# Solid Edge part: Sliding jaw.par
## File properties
Title: Sliding Jaw
Author: Deepak Maini
Template: Normal.par
Last saved by: Robert a Rhodes jr
Revision: 17
Application: Solid Edge
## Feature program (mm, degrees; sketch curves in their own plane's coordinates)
sketch used by "unnamed Protrusion 1" plane through (0, 0, 0) normal (0, -1, 0) x-axis (1, 0, 0)
  line (-34.0632, 44.45) -> (-34.0632, 0)
  line (-34.0632, 0) -> (5.6116, 0)
  line (5.6116, 0) -> (5.6116, 19.9608)
  line (-34.0632, 44.45) -> (-19.6102, 44.45)
  arc centre (-37.2382, 14.3002) radius 34.925 from (-19.6102, 44.45) to (-3.8245, 24.463) cw
  arc centre (2.2507, 26.3108) radius 6.35 from (-3.8245, 24.463) to (2.2507, 19.9608) ccw
  line (5.6116, 19.9608) -> (2.2507, 19.9608)
  dimension (linear) = 37.2382
extrude "unnamed Protrusion 1" add finite 69.7992 symmetric
sketch for "unnamed Protrusion 2" plane through (5.6116, 0, 9.9804) normal (1, 0, 0) x-axis (0, 1, 0)
extrude "unnamed Protrusion 2" add finite 65.0748 along -normal
sketch for "unnamed Cutout 1" plane through (-26.9258, -15.24, -27.8638) normal (0, -1, 0) x-axis (1, 0, 0)
extrude "unnamed Cutout 1" cut through along -normal
sketch for "unnamed Protrusion 3" plane through (5.6116, 0, -9.0696) normal (1, 0, 0) x-axis (0, 1, 0)
  arc centre (0, 26.5956) radius 23.9515 from (-23.8274, 29.0304) to (23.8274, 29.0304) cw
  line (-23.8274, 29.0304) -> (23.8274, 29.0304)
extrude "unnamed Protrusion 3" add through along -normal
sketch for "unnamed Hole 1" plane through (5.6116, 0, -0.1583) normal (1, 0, 0) x-axis (0, 1, 0)
hole "unnamed Hole 1" through
fillet "unnamed Round 1"
sketch for "unnamed Hole 2" plane through (-26.9258, 0, -38.1) normal (0, 0, -1) x-axis (0, 1, 0)
  hole centre (7.9375, 2.3876) bore radius 2.7686
hole "unnamed Hole 2" finite
sketch for "unnamed Hole 3" plane through (-26.9258, 0, -38.1) normal (0, 0, -1) x-axis (0, 1, 0)
  hole centre (-7.9375, 2.3876) bore radius 2.7686
hole "unnamed Hole 3" finite
sketch for "unnamed Hole 4" plane through (-34.0632, 0, 22.225) normal (-1, 0, 0) x-axis (0, -1, 0)
  hole centre (19.0754, 3.175) bore radius 3.175
hole "unnamed Hole 4" finite
sketch for "unnamed Hole 5" plane through (-34.0632, 0, 22.225) normal (-1, 0, 0) x-axis (0, -1, 0)
  hole centre (-19.0246, 3.175) bore radius 3.175
  dimension (linear) = 19.0246
hole "unnamed Hole 5" finite
chamfer "unnamed Chamfer 1"
pattern "unnamed Pattern 1" of "unnamed Hole 2", "unnamed Hole 3"
pattern "unnamed Pattern 2" of "unnamed Hole 4", "unnamed Hole 5"
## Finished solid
Body 1: solid body, 49 faces, 112 edges, 64 vertices.
  Faces by surface: plane 27, cylinder 16, torus 4, sphere 2
  Edges by curve: line 72, circle 33, intersection 7
Bounding box of the edges (mm; curved faces can reach further): 65.075 x 69.799 x 82.550, from (-59.4632, -34.8996, -38.1) to (5.6116, 34.8996, 44.45).
Cylindrical faces by radius (mm): R2.7686 x2, R3.1242 x1, R3.175 x8, R6.35 x2, R9.525 x1, R23.9515 x1, R34.925 x1
Toroidal faces (ring radius, tube radius in mm): R9.525 r3.175 x2, R31.75 r3.175 x2
Spherical faces by radius (mm): R3.175 x2
Planar faces by outward normal: +x 1, +y 4, +z 6, -x 3, -y 4, -z 7, oblique 2
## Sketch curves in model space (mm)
line (-34.0632, 0, 0) -> (5.6116, 0, 0)
line (5.6116, 0, 0) -> (5.6116, 0, 19.9608)
line (5.6116, 0, 19.9608) -> (2.2507, 0, 19.9608)
arc centre (2.2507, 0, 26.3108) radius 6.35 from (-3.8245, 0, 24.463) through (-1.5301, 0, 21.209) to (2.2507, 0, 19.9608)
arc centre (-37.2382, 0, 14.3002) radius 34.925 from (-19.6102, 0, 44.45) through (-9.8305, 0, 35.9468) to (-3.8245, 0, 24.463)
line (-34.0632, 0, 44.45) -> (-19.6102, 0, 44.45)
line (-34.0632, 0, 44.45) -> (-34.0632, 0, 0)
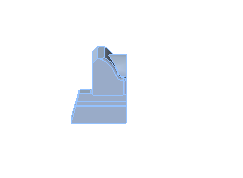
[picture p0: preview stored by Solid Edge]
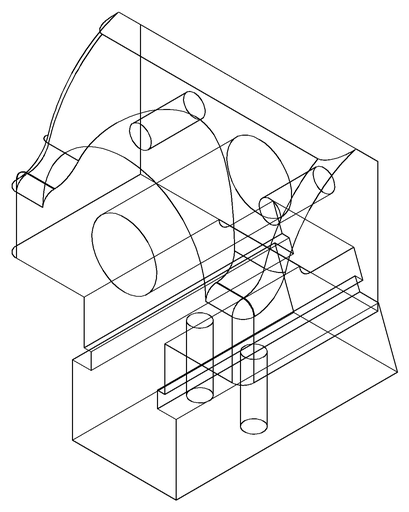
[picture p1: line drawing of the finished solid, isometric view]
